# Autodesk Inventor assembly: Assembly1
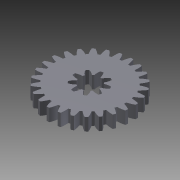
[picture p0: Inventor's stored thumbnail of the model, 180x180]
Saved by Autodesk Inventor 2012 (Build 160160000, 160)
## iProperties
Created: 2018-05
Part Number: Assembly1
Document SubType Name: Assembly
Designer: Elkawokgy
Author: Elkawokgy
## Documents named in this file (4)
- C:\Users\Elkawokgy\Downloads\New folder\Assembly1.iam
- C:\Users\Elkawokgy\Downloads\New folder\Part1.ipt
- C:\Users\Elkawokgy\Downloads\New folder\Assembly1\Design Accelerator\Spur Gears1.iam
- C:\Users\Elkawokgy\Downloads\New folder\Spur Gears3.iam
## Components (3 placed, 2 different names)
1. Part1:1 — Mate:1
2. Spur Gears:1 [sub-assembly] — Mate:1, Mate:2
3. Spur Gears:2 [sub-assembly] — Mate:2
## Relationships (2: Mate 2)
- Mate:1: Part1:1 ↔ Spur Gears:1
- Mate:2: Spur Gears:1 ↔ Spur Gears:2
